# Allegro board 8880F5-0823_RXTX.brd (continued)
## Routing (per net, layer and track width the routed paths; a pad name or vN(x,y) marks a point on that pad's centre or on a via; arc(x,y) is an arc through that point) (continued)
UDBGND:
  vias: v1(117.69,130.81) v1(118.49,128.27) v1(128.57,149.86) v1(128.57,146.05) v1(128.57,138.43) v1(128.57,134.62) v1(130.51,142.24) v1(224.37,298.45) v1(225.17,295.91) v1(452.68,137.92) v1(452.68,134.11) v1(452.68,130.3) v1(454.61,145.54) v1(454.61,141.73) v1(473.29,130.81) v1(474.09,128.27) v1(484.87,130.71) v1(485.12,128.27) v1(512.11,238.76) v1(512.11,234.95) v1(512.11,231.14) v1(512.11,227.33) v1(548.37,300.89) v1(548.62,298.45) v1(557.36,300.99) v1(558.16,298.45)
UT1_UP5V:
  vias: v1(115.19,128.27) v1(115.99,130.81) v1(175.7,264.1) v1(175.7,250.38) v1(175.7,236.67) v1(175.7,222.95) v1(175.7,209.49) v1(175.7,195.52) v1(175.7,182.06) v1(175.7,168.6) v1(175.7,154.88) v1(175.7,141.67) v1(192.47,264.1) v1(192.47,250.38) v1(192.47,236.67) v1(192.47,222.95) v1(192.47,209.49) v1(192.47,195.52) v1(192.47,182.06) v1(192.47,168.6) v1(192.47,154.88) v1(208.98,264.1) v1(209.23,250.38) v1(209.23,236.67) v1(209.23,222.95) v1(209.23,209.49) v1(209.23,195.52) v1(209.49,182.06) v1(209.49,168.6) v1(209.49,155.13) v1(221.87,295.91) v1(222.67,298.45) v1(232.25,271.67) v1(244.8,288.61) v1(250.5,296.86) v1(256.73,132.14) v1(263.71,296.86) v1(269.94,135.19) v1(273.24,272.1) v1(277.17,296.86) v1(282.9,147.38) v1(290.64,296.86) v1(293.31,272.1) v1(303.84,296.86) v1(304.61,152.34) v1(304.61,139.64) v1(312.25,271.67) v1(317.05,296.86) v1(318.32,139.64) v1(330.51,296.86) v1(343.98,296.86) v1(354.27,138.37) v1(369.38,265.11) v1(369.38,249.11) v1(369.38,232.6) v1(369.63,297.12) v1(369.63,281.11) v1(375.22,188.15) v1(375.22,171.39) v1(376.23,217.11) v1(383.09,297.12) v1(383.09,281.11) v1(383.09,265.11) v1(383.09,249.11) v1(383.09,232.85) v1(383.73,202.38) v1(384.36,139.89) v1(388.43,188.15) v1(388.43,171.64) v1(388.43,154.88) v1(389.7,217.36) v1(396.55,297.12) v1(396.55,281.11) v1(396.55,265.37) v1(396.55,249.11) v1(396.55,233.11) v1(397.57,139.89) v1(400.24,202.38) v1(401.89,188.15) v1(401.89,171.64) v1(402.14,154.88) v1(403.41,217.61) v1(410.27,265.37) v1(410.52,297.12) v1(410.52,281.37) v1(410.52,249.11) v1(410.78,139.89) v1(415.1,171.64) v1(415.6,154.88) v1(423.61,188.92) v1(470.79,128.27) v1(471.59,130.81) v1(482.62,128.27) v1(483.17,130.71) v1(546.12,298.45) v1(546.67,300.89) v1(554.86,298.45) v1(555.66,300.99)
N26125600: length 3
  BOTTOM w0.119: R55.2 211.29,259.17 210.81,258.7 K25.3
N26125602: length 3
  BOTTOM w0.119: R56.1 211.29,256.03 210.81,256.5 K25.4
N26125604: length 3
  BOTTOM w0.119: K25.6 199.14,258.7 198.67,259.17 R57.2
N26125606: length 3
  BOTTOM w0.119: K25.5 199.14,256.5 198.67,256.03 R58.1
N26125622: length 3
  BOTTOM w0.119: R59.2 194.78,245.46 194.3,244.98 K26.3
N26125624: length 3
  BOTTOM w0.119: R60.1 194.78,242.31 194.3,242.78 K26.4
N26125626: length 3
  BOTTOM w0.119: R61.2 182.16,245.46 182.63,244.98 K26.6
N26125628: length 3
  BOTTOM w0.119: R62.1 182.16,242.31 182.63,242.78 K26.5
N26125644: length 3
  BOTTOM w0.119: K27.5 165.87,242.78 165.4,242.31 R66.1
N26125646: length 3
  BOTTOM w0.119: R65.2 165.4,245.46 165.87,244.98 K27.6
N26125685: length 3
  BOTTOM w0.119: K22.6 199.4,244.98 198.92,245.46 R45.2
N26125687: length 3
  BOTTOM w0.119: K22.5 199.4,242.78 198.92,242.31 R46.1
N26125689: length 3
  BOTTOM w0.119: K23.3 194.3,231.27 194.78,231.74 R47.2
N26125691: length 3
  BOTTOM w0.119: R48.1 194.78,228.6 194.3,229.07 K23.4
N26125693: length 3
  BOTTOM w0.119: R49.2 182.16,231.74 182.63,231.27 K23.6
N26125695: length 3
  BOTTOM w0.119: K23.5 182.63,229.07 182.16,228.6 R50.1
N26125711: length 3
  BOTTOM w0.119: R51.2 178.01,231.74 177.54,231.27 K24.3
N26125713: length 3
  BOTTOM w0.119: K24.4 177.54,229.07 178.01,228.6 R52.1
N26125715: length 3
  BOTTOM w0.119: K24.6 165.87,231.27 165.4,231.74 R53.2
N26125717: length 3
  BOTTOM w0.119: K24.5 165.87,229.07 165.4,228.6 R54.1
N26125746: length 3
  BOTTOM w0.119: R102.2 211.54,245.46 211.07,244.98 K22.3
N26125748: length 3
  BOTTOM w0.119: R103.1 211.54,242.31 211.07,242.78 K22.4
N26125750: length 3
  BOTTOM w0.119: R104.2 178.01,245.46 177.54,244.98 K27.3
N26125752: length 3
  BOTTOM w0.119: K27.4 177.54,242.78 178.01,242.31 R105.1
N26323523: length 3
  BOTTOM w0.119: K17.3 255.9,298.7 255.43,299.17 R71.2
N26323525: length 3
  BOTTOM w0.119: K17.4 258.1,298.7 258.58,299.17 R72.1
N26323527: length 3
  BOTTOM w0.119: R74.1 258.58,286.55 258.1,287.03 K17.5
N26323529: length 3
  BOTTOM w0.119: K17.6 255.9,287.03 255.43,286.55 R73.2
N26323531: length 3
  BOTTOM w0.119: K21.3 282.57,298.7 282.1,299.17 R75.2
N26323533: length 3
  BOTTOM w0.119: K21.4 284.77,298.7 285.25,299.17 R76.1
N26323535: length 3
  BOTTOM w0.119: K21.5 284.77,287.03 285.25,286.55 R78.1
N26323537: length 3
  BOTTOM w0.119: K21.6 282.57,287.03 282.1,286.55 R77.2
N26323539: length 3
  BOTTOM w0.119: K29.3 177.54,258.7 178.01,259.17 R79.2
N26323541: length 3
  BOTTOM w0.119: R80.1 178.01,256.03 177.54,256.5 K29.4
N26323543: length 3
  BOTTOM w0.119: K29.6 165.87,258.7 165.4,259.17 R43.2
N26323545: length 3
  BOTTOM w0.119: R44.1 165.4,256.03 165.87,256.5 K29.5
N26323547: length 3
  BOTTOM w0.119: R63.2 194.78,259.17 194.3,258.7 K30.3
N26323549: length 3
  BOTTOM w0.119: K30.4 194.3,256.5 194.78,256.03 R64.1
N26323551: length 3
  BOTTOM w0.119: R101.1 182.16,256.03 182.63,256.5 K30.5
N26323553: length 3
  BOTTOM w0.119: K30.6 182.63,258.7 182.16,259.17 R100.2
N26325241: length 3
  BOTTOM w0.119: R67.2 239.87,286.3 239.4,286.77 K16.3
N26325243: length 3
  BOTTOM w0.119: K16.4 237.2,286.77 236.72,286.3 R68.1
N26325245: length 3
  BOTTOM w0.119: K16.5 237.2,298.44 236.72,298.92 R70.1
N26325247: length 3
  BOTTOM w0.119: R69.2 239.87,298.92 239.4,298.44 K16.6
N26326910: length 3
  BOTTOM w0.119: K6.5 338.11,287.03 338.59,286.55 R30.1
N26326941: length 3
  BOTTOM w0.119: R27.2 335.44,299.17 335.91,298.7 K6.3
N26326943: length 3
  BOTTOM w0.119: K6.4 338.11,298.7 338.59,299.17 R28.1
N26326945: length 3
  BOTTOM w0.119: K6.6 335.91,287.03 335.44,286.55 R29.2
N26326947: length 3
  BOTTOM w0.119: R34.1 325.12,286.55 324.65,287.03 K7.5
N26326959: length 3
  BOTTOM w0.119: K7.3 322.45,298.7 321.98,299.17 R31.2
N26326961: length 3
  BOTTOM w0.119: R32.1 325.12,299.17 324.65,298.7 K7.4
N26326963: length 3
  BOTTOM w0.119: R33.2 321.98,286.55 322.45,287.03 K7.6
N26327095: length 3
  BOTTOM w0.119: K11.3 287.91,270.26 288.38,269.79 R39.2
N26327097: length 3
  BOTTOM w0.119: K11.4 285.71,270.26 285.24,269.79 R40.1
N26327099: length 3
  BOTTOM w0.119: K8.5 271.31,287.03 271.78,286.55 R38.1
N26327103: length 3
  BOTTOM w0.119: R37.2 268.64,286.55 269.11,287.03 K8.6
N26327105: length 3
  BOTTOM w0.119: K11.6 287.91,281.93 288.38,282.41 R41.2
N26327107: length 3
  BOTTOM w0.119: R42.1 285.24,282.41 285.71,281.93 K11.5
N26328546: length 3
  BOTTOM w0.119: K5.5 351.58,287.03 352.05,286.55 R26.1
N26328550: length 3
  BOTTOM w0.119: R23.2 348.9,299.17 349.38,298.7 K5.3
N26328552: length 3
  BOTTOM w0.119: R24.1 352.05,299.17 351.58,298.7 K5.4
N26328554: length 3
  BOTTOM w0.119: K5.6 349.38,287.03 348.9,286.55 R25.2
N26330264: length 3
  BOTTOM w0.119: K3.5 298.24,287.03 298.71,286.55 R18.1
N26330266: length 3
  BOTTOM w0.119: R17.2 295.56,286.55 296.04,287.03 K3.6
N26330268: length 3
  BOTTOM w0.119: R16.1 298.71,299.17 298.24,298.7 K3.4
N26330270: length 3
  BOTTOM w0.119: K3.3 296.04,298.7 295.56,299.17 R15.2
N26330276: length 3
  BOTTOM w0.119: K1.5 165.87,215.35 165.4,214.88 R10.1
N26330278: length 3
  BOTTOM w0.119: K1.6 165.87,217.55 165.4,218.02 R9.2
N26330280: length 3
  BOTTOM w0.119: R8.1 178.01,214.88 177.54,215.35 K1.4
N26330282: length 3
  BOTTOM w0.119: R7.2 178.01,218.02 177.54,217.55 K1.3
N26330286: length 3
  BOTTOM w0.119: K2.3 211.07,231.27 211.54,231.74 R11.2
N26330288: length 3
  BOTTOM w0.119: R12.1 211.54,228.6 211.07,229.07 K2.4
N26330290: length 3
  BOTTOM w0.119: R22.1 311.92,286.55 311.44,287.03 K4.5
N26330294: length 3
  BOTTOM w0.119: R19.2 308.77,299.17 309.24,298.7 K4.3
N26330296: length 3
  BOTTOM w0.119: K4.4 311.44,298.7 311.92,299.17 R20.1
N26330298: length 3
  BOTTOM w0.119: K4.6 309.24,287.03 308.77,286.55 R21.2
N26330300: length 3
  BOTTOM w0.119: R14.1 198.92,228.6 199.4,229.07 K2.5
N26330302: length 3
  BOTTOM w0.119: R13.2 198.92,231.74 199.4,231.27 K2.6
N26336828:
  vias: v1(222.38,273.82) v1(222.38,272.66) v1(224.65,271.67)
N26336832:
  vias: v1(222.38,275.98) v1(222.38,274.82) v1(224.65,276.97)
N26336834:
  vias: v1(221.21,276.98) v1(222.38,276.98)
N26336836:
  vias: v1(221.21,271.66) v1(222.38,271.66)
N26486525: length 3
  BOTTOM w0.119: UNK2K25.3 401.95,234.94 401.48,235.42 UNK2R55.2
N26486526: length 3
  BOTTOM w0.119: UNK2R56.1 404.63,235.42 404.15,234.94 UNK2K25.4
N26486527: length 3
  BOTTOM w0.119: UNK2R57.2 401.48,222.8 401.95,223.27 UNK2K25.6
N26486528: length 3
  BOTTOM w0.119: UNK2R58.1 404.63,222.8 404.15,223.27 UNK2K25.5
N26486530: length 3
  BOTTOM w0.119: UNK2K26.3 395.1,219.2 394.62,219.67 UNK2R59.2
N26486531: length 3
  BOTTOM w0.119: UNK2R60.1 397.77,219.67 397.3,219.2 UNK2K26.4
N26486532: length 3
  BOTTOM w0.119: UNK2R61.2 394.62,207.05 395.1,207.52 UNK2K26.6
N26486533: length 3
  BOTTOM w0.119: UNK2R62.1 397.77,207.05 397.3,207.52 UNK2K26.5
N26486535: length 3
  BOTTOM w0.119: UNK2K27.5 383.83,207.27 384.31,206.8 UNK2R66.1
N26486536: length 3
  BOTTOM w0.119: UNK2K27.6 381.63,207.27 381.16,206.8 UNK2R65.2
N26486543: length 3
  BOTTOM w0.119: UNK2R45.2 374.3,222.29 374.78,222.76 UNK2K22.6
N26486544: length 3
  BOTTOM w0.119: UNK2R46.1 377.45,222.29 376.98,222.76 UNK2K22.5
N26486545: length 3
  BOTTOM w0.119: UNK2K23.3 388.49,234.69 388.02,235.16 UNK2R47.2
N26486546: length 3
  BOTTOM w0.119: UNK2R48.1 391.16,235.16 390.69,234.69 UNK2K23.4
N26486547: length 3
  BOTTOM w0.119: UNK2R49.2 388.02,222.55 388.49,223.02 UNK2K23.6
N26486548: length 3
  BOTTOM w0.119: UNK2R50.1 391.16,222.55 390.69,223.02 UNK2K23.5
N26486550: length 3
  BOTTOM w0.119: UNK2K24.3 388.49,250.95 388.02,251.42 UNK2R51.2
N26486551: length 3
  BOTTOM w0.119: UNK2K24.4 390.69,250.95 391.16,251.42 UNK2R52.1
N26486552: length 3
  BOTTOM w0.119: UNK2R53.2 388.02,238.8 388.49,239.27 UNK2K24.6
N26486553: length 3
  BOTTOM w0.119: UNK2R54.1 391.16,238.8 390.69,239.27 UNK2K24.5
N26486568: length 3
  BOTTOM w0.119: UNK2K22.3 374.78,234.44 374.3,234.91 UNK2R102.2
N26486569: length 3
  BOTTOM w0.119: UNK2K22.4 376.98,234.44 377.45,234.91 UNK2R103.1
N26486570: length 3
  BOTTOM w0.119: UNK2R104.2 381.16,219.41 381.63,218.94 UNK2K27.3
N26486571: length 3
  BOTTOM w0.119: UNK2R105.1 384.31,219.41 383.83,218.94 UNK2K27.4
N26486686:
  vias: v1(465.57,235.71)
N26486691:
  vias: v1(468.62,235.71)
N26486726:
  vias: v1(374.56,299.91) v1(375.03,297.12)
N26486727:
  vias: v1(377.23,297.12) v1(377.7,299.91)
N26486728:
  vias: v1(377.23,289.12) v1(377.7,286.32)
N26486729:
  vias: v1(374.56,286.32) v1(375.03,289.12)
N26486730:
  vias: v1(401.48,299.91) v1(401.95,297.12)
N26486731:
  vias: v1(404.15,297.12) v1(404.63,299.91)
N26486732:
  vias: v1(404.15,289.12) v1(404.63,286.32)
N26486733:
  vias: v1(401.48,286.32) v1(401.95,289.12)
N26486734: length 3
  BOTTOM w0.119: UNK2R79.2 374.3,251.42 374.78,250.95 UNK2K29.3
N26486735: length 3
  BOTTOM w0.119: UNK2K29.4 376.98,250.95 377.45,251.42 UNK2R80.1
N26486736: length 3
  BOTTOM w0.119: UNK2K29.6 374.78,239.27 374.3,238.8 UNK2R43.2
N26486737: length 3
  BOTTOM w0.119: UNK2K29.5 376.98,239.27 377.45,238.8 UNK2R44.1
N26486738: length 3
  BOTTOM w0.119: UNK2R63.2 415.45,251.42 415.92,250.95 UNK2K30.3
N26486739: length 3
  BOTTOM w0.119: UNK2K30.4 418.12,250.95 418.6,251.42 UNK2R64.1
N26486740: length 3
  BOTTOM w0.119: UNK2K30.5 418.12,239.27 418.6,238.8 UNK2R101.1
N26486741: length 3
  BOTTOM w0.119: UNK2R100.2 415.45,238.8 415.92,239.27 UNK2K30.6
N26486822:
  vias: v1(374.3,267.91) v1(374.78,265.11)
N26486823:
  vias: v1(376.98,265.11) v1(377.45,267.91)
N26486824:
  vias: v1(376.98,257.11) v1(377.45,254.32)
N26486825:
  vias: v1(374.3,254.32) v1(374.78,257.11)
N26486847:
  vias: v1(404.15,273.11) v1(404.63,270.32)
N26486849:
  vias: v1(401.48,283.91) v1(401.95,281.11)
N26486850:
  vias: v1(404.15,281.11) v1(404.63,283.91)
N26486851:
  vias: v1(401.48,270.32) v1(401.95,273.11)
N26486852:
  vias: v1(390.69,273.11) v1(391.16,270.32)
N26486854:
  vias: v1(388.02,283.91) v1(388.49,281.11)
N26486855:
  vias: v1(390.69,281.11) v1(391.16,283.91)
N26486856:
  vias: v1(388.02,270.32) v1(388.49,273.11)
N26486898:
  vias: v1(415.2,268.16)
N26486899:
  vias: v1(418.34,268.16)
N26486900:
  vias: v1(390.69,289.12) v1(391.16,286.32)
N26486902:
  vias: v1(388.02,286.32) v1(388.49,289.12)
N26486903:
  vias: v1(415.2,254.57) v1(415.67,257.37)
N26486904:
  vias: v1(417.87,257.37) v1(418.34,254.57)
N26486946:
  vias: v1(404.15,257.37) v1(404.63,254.57)
N26486948:
  vias: v1(401.48,268.16) v1(401.95,265.37)
N26486949:
  vias: v1(404.15,265.37) v1(404.63,268.16)
N26486950:
  vias: v1(401.48,254.57) v1(401.95,257.37)
N26486971: length 3
  BOTTOM w0.119: UNK2R18.1 404.63,238.8 404.15,239.27 UNK2K3.5
N26486972: length 3
  BOTTOM w0.119: UNK2R17.2 401.48,238.8 401.95,239.27 UNK2K3.6
N26486973: length 3
  BOTTOM w0.119: UNK2K3.4 404.15,250.95 404.63,251.42 UNK2R16.1
N26486974: length 3
  BOTTOM w0.119: UNK2K3.3 401.95,250.95 401.48,251.42 UNK2R15.2
N26486977: length 3
  BOTTOM w0.119: UNK2K1.5 418.12,287.28 418.6,286.81 UNK2R10.1
N26486978: length 3
  BOTTOM w0.119: UNK2R9.2 415.45,286.81 415.92,287.28 UNK2K1.6
N26486979: length 3
  BOTTOM w0.119: UNK2R8.1 418.6,299.42 418.12,298.95 UNK2K1.4
N26486980: length 3
  BOTTOM w0.119: UNK2R7.2 415.45,299.42 415.92,298.95 UNK2K1.3
N26486982:
  vias: v1(415.45,284.16)
N26486983:
  vias: v1(418.6,284.16)
N26486984:
  vias: v1(377.23,273.11) v1(377.7,270.32)
N26486986:
  vias: v1(374.56,283.91) v1(375.03,281.11)
N26486987:
  vias: v1(377.23,281.11) v1(377.7,283.91)
N26486988:
  vias: v1(374.56,270.32) v1(375.03,273.11)
N26486989: length 3
  BOTTOM w0.119: UNK2R14.1 418.6,271.01 418.12,271.48 UNK2K2.5
N26486990: length 3
  BOTTOM w0.119: UNK2R13.2 415.45,270.98 415.92,271.45 UNK2K2.6
N26487182:
  vias: v1(456.25,233.88)
N26487183:
  vias: v1(451.68,233.88)
N26487190:
  vias: v1(302.38,273.82) v1(302.38,272.66) v1(304.65,271.67)
N26487192:
  vias: v1(302.38,275.98) v1(302.38,274.82) v1(304.65,276.97)
N26487193:
  vias: v1(301.21,276.98) v1(302.38,276.98)
N26487194:
  vias: v1(301.21,271.66) v1(302.38,271.66)
N26487223:
  vias: v1(451.62,232.41)
N26487224:
  vias: v1(451.62,224.79)
N26487285:
  vias: v1(483.1,233.68)
N26487289:
  vias: v1(483.1,241.3)
N26491412:
  vias: v1(491.1,226.67)
N26491416:
  vias: v1(490.86,212.91)
N26491418:
  vias: v1(485.8,212.91)
N26491425:
  vias: v1(477.53,218.59)
N26491459:
  vias: v1(477.43,204.98)
N26491497:
  vias: v1(485.8,226.62)
N26495382: length 3
  BOTTOM w0.119: UNK3R55.2 211.79,163.67 211.32,163.2 UNK3K25.3
N26495383: length 3
  BOTTOM w0.119: UNK3R56.1 211.79,160.52 211.32,161 UNK3K25.4
N26495384: length 3
  BOTTOM w0.119: UNK3K25.6 199.65,163.2 199.18,163.67 UNK3R57.2
N26495385: length 3
  BOTTOM w0.119: UNK3K25.5 199.65,161 199.18,160.52 UNK3R58.1
N26495387: length 3
  BOTTOM w0.119: UNK3R59.2 194.78,163.67 194.3,163.2 UNK3K26.3
N26495388: length 3
  BOTTOM w0.119: UNK3R60.1 194.78,160.52 194.3,161 UNK3K26.4
N26495389: length 3
  BOTTOM w0.119: UNK3K26.6 182.63,163.2 182.16,163.67 UNK3R61.2
N26495390: length 3
  BOTTOM w0.119: UNK3K26.5 182.63,161 182.16,160.52 UNK3R62.1
N26495392: length 3
  BOTTOM w0.119: UNK3R66.1 199.18,173.99 199.65,174.46 UNK3K27.5
N26495393: length 3
  BOTTOM w0.119: UNK3K27.6 199.65,176.66 199.18,177.13 UNK3R65.2
N26495400: length 3
  BOTTOM w0.119: UNK3R45.2 199.18,150.21 199.65,149.73 UNK3K22.6
N26495401: length 3
  BOTTOM w0.119: UNK3R46.1 199.18,147.06 199.65,147.53 UNK3K22.5
N26495402: length 3
  BOTTOM w0.119: UNK3K23.3 177.54,136.27 178.01,136.74 UNK3R47.2
N26495403: length 3
  BOTTOM w0.119: UNK3K23.4 177.54,134.07 178.01,133.6 UNK3R48.1
N26495404: length 3
  BOTTOM w0.119: UNK3K23.6 165.87,136.27 165.4,136.74 UNK3R49.2
N26495405: length 3
  BOTTOM w0.119: UNK3R50.1 165.4,133.6 165.87,134.07 UNK3K23.5
N26495407: length 3
  BOTTOM w0.119: UNK3K24.3 194.3,149.48 194.78,149.95 UNK3R51.2
N26495408: length 3
  BOTTOM w0.119: UNK3R52.1 194.78,146.81 194.3,147.28 UNK3K24.4
N26495409: length 3
  BOTTOM w0.119: UNK3K24.6 182.63,149.48 182.16,149.95 UNK3R53.2
N26495410: length 3
  BOTTOM w0.119: UNK3K24.5 182.63,147.28 182.16,146.81 UNK3R54.1
N26495425: length 3
  BOTTOM w0.119: UNK3K22.3 211.32,149.73 211.79,150.21 UNK3R102.2
N26495426: length 3
  BOTTOM w0.119: UNK3K22.4 211.32,147.53 211.79,147.06 UNK3R103.1
N26495427: length 3
  BOTTOM w0.119: UNK3R104.2 211.79,177.13 211.32,176.66 UNK3K27.3
N26495428: length 3
  BOTTOM w0.119: UNK3R105.1 211.79,173.99 211.32,174.46 UNK3K27.4
N26495583: length 3
  BOTTOM w0.119: UNK3K17.3 177.54,190.12 178.01,190.59 UNK3R71.2
N26495584: length 3
  BOTTOM w0.119: UNK3R72.1 178.01,187.45 177.54,187.92 UNK3K17.4
N26495585: length 3
  BOTTOM w0.119: UNK3K17.5 165.87,187.92 165.4,187.45 UNK3R74.1
N26495586: length 3
  BOTTOM w0.119: UNK3R73.2 165.4,190.59 165.87,190.12 UNK3K17.6
N26495587: length 3
  BOTTOM w0.119: UNK3R75.2 211.54,190.59 211.07,190.12 UNK3K21.3
N26495588: length 3
  BOTTOM w0.119: UNK3R76.1 211.54,187.45 211.07,187.92 UNK3K21.4
N26495589: length 3
  BOTTOM w0.119: UNK3K21.5 199.4,187.92 198.92,187.45 UNK3R78.1
N26495590: length 3
  BOTTOM w0.119: UNK3K21.6 199.4,190.12 198.92,190.59 UNK3R77.2
N26495591: length 3
  BOTTOM w0.119: UNK3R79.2 178.01,163.67 177.54,163.2 UNK3K29.3
N26495592: length 3
  BOTTOM w0.119: UNK3K29.4 177.54,161 178.01,160.52 UNK3R80.1
N26495593: length 3
  BOTTOM w0.119: UNK3R43.2 165.4,163.67 165.87,163.2 UNK3K29.6
N26495594: length 3
  BOTTOM w0.119: UNK3R44.1 165.4,160.52 165.87,161 UNK3K29.5
N26495595: length 3
  BOTTOM w0.119: UNK3K30.3 177.54,149.48 178.01,149.95 UNK3R63.2
N26495596: length 3
  BOTTOM w0.119: UNK3R64.1 178.01,146.81 177.54,147.28 UNK3K30.4
N26495597: length 3
  BOTTOM w0.119: UNK3K30.5 165.87,147.28 165.4,146.81 UNK3R101.1
N26495598: length 3
  BOTTOM w0.119: UNK3R100.2 165.4,149.95 165.87,149.48 UNK3K30.6
N26495679: length 3
  BOTTOM w0.119: UNK3R67.2 211.54,204.56 211.07,204.09 UNK3K16.3
N26495680: length 3
  BOTTOM w0.119: UNK3R68.1 211.54,201.42 211.07,201.89 UNK3K16.4
N26495681: length 3
  BOTTOM w0.119: UNK3K16.5 199.4,201.89 198.92,201.42 UNK3R70.1
N26495682: length 3
  BOTTOM w0.119: UNK3K16.6 199.4,204.09 198.92,204.56 UNK3R69.2
N26495704: length 3
  BOTTOM w0.119: UNK3K6.5 199.4,215.35 198.92,214.88 UNK3R30.1
N26495706: length 3
  BOTTOM w0.119: UNK3R27.2 211.54,218.02 211.07,217.55 UNK3K6.3
N26495707: length 3
  BOTTOM w0.119: UNK3K6.4 211.07,215.35 211.54,214.88 UNK3R28.1
N26495708: length 3
  BOTTOM w0.119: UNK3K6.6 199.4,217.55 198.92,218.02 UNK3R29.2
N26495709: length 3
  BOTTOM w0.119: UNK3R34.1 182.16,201.42 182.63,201.89 UNK3K7.5
N26495711: length 3
  BOTTOM w0.119: UNK3K7.3 194.3,204.09 194.78,204.56 UNK3R31.2
N26495712: length 3
  BOTTOM w0.119: UNK3R32.1 194.78,201.42 194.3,201.89 UNK3K7.4
N26495713: length 3
  BOTTOM w0.119: UNK3R33.2 182.16,204.56 182.63,204.09 UNK3K7.6
N26495755: length 3
  BOTTOM w0.119: UNK3R39.2 178.01,204.56 177.54,204.09 UNK3K11.3
N26495756: length 3
  BOTTOM w0.119: UNK3K11.4 177.54,201.89 178.01,201.42 UNK3R40.1
N26495757: length 3
  BOTTOM w0.119: UNK3R38.1 182.16,187.45 182.63,187.92 UNK3K8.5
N26495759: length 3
  BOTTOM w0.119: UNK3K8.6 182.63,190.12 182.16,190.59 UNK3R37.2
N26495760: length 3
  BOTTOM w0.119: UNK3R41.2 165.4,204.56 165.87,204.09 UNK3K11.6
N26495761: length 3
  BOTTOM w0.119: UNK3R42.1 165.4,201.42 165.87,201.89 UNK3K11.5
N26495803: length 3
  BOTTOM w0.119: UNK3K5.5 182.63,215.35 182.16,214.88 UNK3R26.1
N26495805: length 3
  BOTTOM w0.119: UNK3R23.2 194.78,218.02 194.3,217.55 UNK3K5.3
N26495806: length 3
  BOTTOM w0.119: UNK3R24.1 194.78,214.88 194.3,215.35 UNK3K5.4
N26495807: length 3
  BOTTOM w0.119: UNK3R25.2 182.16,218.02 182.63,217.55 UNK3K5.6
N26495828: length 3
  BOTTOM w0.119: UNK3K3.5 262.34,145.03 261.87,145.5 UNK3R18.1
N26495829: length 3
  BOTTOM w0.119: UNK3R17.2 265.01,145.5 264.54,145.03 UNK3K3.6
N26495830: length 3
  BOTTOM w0.119: UNK3R16.1 261.87,132.88 262.34,133.36 UNK3K3.4
N26495831: length 3
  BOTTOM w0.119: UNK3K3.3 264.54,133.36 265.01,132.88 UNK3R15.2
N26495834: length 3
  BOTTOM w0.119: UNK3K1.5 275.3,157.22 274.82,157.69 UNK3R10.1
N26495835: length 3
  BOTTOM w0.119: UNK3K1.6 277.5,157.22 277.97,157.69 UNK3R9.2
N26495836: length 3
  BOTTOM w0.119: UNK3K1.4 275.3,145.55 274.82,145.08 UNK3R8.1
N26495837: length 3
  BOTTOM w0.119: UNK3K1.3 277.5,145.55 277.97,145.08 UNK3R7.2
N26495839: length 3
  BOTTOM w0.119: UNK3K2.3 251.33,130.31 251.81,129.84 UNK3R11.2
N26495840: length 3
  BOTTOM w0.119: UNK3R12.1 248.66,129.84 249.13,130.31 UNK3K2.4
N26495841: length 3
  BOTTOM w0.119: UNK3K4.5 165.93,174.46 165.46,173.99 UNK3R22.1
N26495843: length 3
  BOTTOM w0.119: UNK3K4.3 177.54,176.66 178.01,177.13 UNK3R19.2
N26495844:
  vias: v1(175.7,174.46) v1(178.5,173.99)
N26495845: length 3
  BOTTOM w0.119: UNK3R21.2 165.4,177.13 165.87,176.66 UNK3K4.6
N26495846: length 3
  BOTTOM w0.119: UNK3K2.5 249.13,141.98 248.66,142.45 UNK3R14.1
N26495847: length 3
  BOTTOM w0.119: UNK3R13.2 251.81,142.45 251.33,141.98 UNK3K2.6
N26504239: length 3
  BOTTOM w0.119: UNK4R55.2 393.35,190.46 393.83,189.99 UNK4K25.3
N26504240: length 3
  BOTTOM w0.119: UNK4K25.4 396.03,189.99 396.5,190.46 UNK4R56.1
N26504241: length 3
  BOTTOM w0.119: UNK4R57.2 393.35,177.84 393.83,178.31 UNK4K25.6
N26504242: length 3
  BOTTOM w0.119: UNK4R58.1 396.5,177.84 396.03,178.31 UNK4K25.5
N26504244: length 3
  BOTTOM w0.119: UNK4K26.3 407.29,189.99 406.82,190.46 UNK4R59.2
N26504245: length 3
  BOTTOM w0.119: UNK4K26.4 409.49,189.99 409.96,190.46 UNK4R60.1
N26504246: length 3
  BOTTOM w0.119: UNK4K26.6 407.29,178.31 406.82,177.84 UNK4R61.2
N26504247: length 3
  BOTTOM w0.119: UNK4R62.1 409.96,177.84 409.49,178.31 UNK4K26.5
N26504249: length 3
  BOTTOM w0.119: UNK4R66.1 383.29,161.08 382.82,161.55 UNK4K27.5
N26504250: length 3
  BOTTOM w0.119: UNK4R65.2 380.15,161.08 380.62,161.55 UNK4K27.6
N26504257: length 3
  BOTTOM w0.119: UNK4K22.6 373.89,196.98 373.42,197.45 UNK4R45.2
N26504258: length 3
  BOTTOM w0.119: UNK4K22.5 373.89,194.78 373.42,194.31 UNK4R46.1
N26504259: length 3
  BOTTOM w0.119: UNK4R47.2 402.55,197.45 402.08,196.98 UNK4K23.3
N26504260: length 3
  BOTTOM w0.119: UNK4R48.1 402.55,194.31 402.08,194.78 UNK4K23.4
N26504261: length 3
  BOTTOM w0.119: UNK4K23.6 390.4,196.98 389.93,197.45 UNK4R49.2
N26504262: length 3
  BOTTOM w0.119: UNK4K23.5 390.4,194.78 389.93,194.31 UNK4R50.1
N26504264: length 3
  BOTTOM w0.119: UNK4K24.3 356.1,132.97 356.57,133.44 UNK4R51.2
N26504265: length 3
  BOTTOM w0.119: UNK4K24.4 356.1,130.77 356.57,130.3 UNK4R52.1
N26504266: length 3
  BOTTOM w0.119: UNK4K24.6 344.43,132.97 343.96,133.44 UNK4R53.2
N26504267: length 3
  BOTTOM w0.119: UNK4R54.1 343.96,130.3 344.43,130.77 UNK4K24.5
N26504282: length 3
  BOTTOM w0.119: UNK4K22.3 385.57,196.98 386.04,197.45 UNK4R102.2
N26504283: length 3
  BOTTOM w0.119: UNK4K22.4 385.57,194.78 386.04,194.31 UNK4R103.1
N26504284: length 3
  BOTTOM w0.119: UNK4K27.3 380.62,173.22 380.15,173.69 UNK4R104.2
N26504285: length 3
  BOTTOM w0.119: UNK4R105.1 383.29,173.69 382.82,173.22 UNK4K27.4
N26504400:
  vias: v1(465.57,192.28)
N26504405:
  vias: v1(468.62,192.28)
N26504440: length 3
  BOTTOM w0.119: UNK4K17.3 416.18,141.73 415.71,142.2 UNK4R71.2
N26504441: length 3
  BOTTOM w0.119: UNK4R72.1 418.85,142.2 418.38,141.73 UNK4K17.4
N26504442: length 3
  BOTTOM w0.119: UNK4K17.5 418.38,130.05 418.85,129.58 UNK4R74.1
N26504443: length 3
  BOTTOM w0.119: UNK4R73.2 415.71,129.58 416.18,130.05 UNK4K17.6
N26504444: length 3
  BOTTOM w0.119: UNK4R75.2 389.29,142.2 389.76,141.73 UNK4K21.3
N26504445: length 3
  BOTTOM w0.119: UNK4R76.1 392.43,142.2 391.96,141.73 UNK4K21.4
N26504446: length 3
  BOTTOM w0.119: UNK4K21.5 391.96,130.05 392.43,129.58 UNK4R78.1
N26504447: length 3
  BOTTOM w0.119: UNK4R77.2 389.29,129.58 389.76,130.05 UNK4K21.6
N26504448: length 3
  BOTTOM w0.119: UNK4R79.2 406.82,173.95 407.29,173.48 UNK4K29.3
N26504449: length 3
  BOTTOM w0.119: UNK4K29.4 409.49,173.48 409.96,173.95 UNK4R80.1
N26504450: length 3
  BOTTOM w0.119: UNK4R43.2 406.82,161.33 407.29,161.8 UNK4K29.6
N26504451: length 3
  BOTTOM w0.119: UNK4K29.5 409.49,161.8 409.96,161.33 UNK4R44.1
N26504452: length 3
  BOTTOM w0.119: UNK4K30.3 310.01,154.17 309.53,154.64 UNK4R63.2
N26504453: length 3
  BOTTOM w0.119: UNK4R64.1 312.68,154.64 312.21,154.17 UNK4K30.4
N26504454: length 3
  BOTTOM w0.119: UNK4K30.5 312.21,142.5 312.68,142.03 UNK4R101.1
N26504455: length 3
  BOTTOM w0.119: UNK4K30.6 310.01,142.5 309.53,142.03 UNK4R100.2
N26504536: length 3
  BOTTOM w0.119: UNK4R67.2 393.35,173.95 393.83,173.48 UNK4K16.3
N26504537: length 3
  BOTTOM w0.119: UNK4K16.4 396.03,173.48 396.5,173.95 UNK4R68.1
N26504538: length 3
  BOTTOM w0.119: UNK4K16.5 396.03,161.8 396.5,161.33 UNK4R70.1
N26504539: length 3
  BOTTOM w0.119: UNK4R69.2 393.35,161.33 393.83,161.8 UNK4K16.6
N26504561: length 3
  BOTTOM w0.119: UNK4R30.1 396.5,144.57 396.03,145.04 UNK4K6.5
N26504563: length 3
  BOTTOM w0.119: UNK4R27.2 393.35,157.18 393.83,156.71 UNK4K6.3
N26504564: length 3
  BOTTOM w0.119: UNK4K6.4 396.03,156.71 396.5,157.18 UNK4R28.1
N26504565: length 3
  BOTTOM w0.119: UNK4R29.2 393.35,144.57 393.83,145.04 UNK4K6.6
N26504566: length 3
  BOTTOM w0.119: UNK4K7.5 413.77,181.32 413.3,180.84 UNK4R34.1
N26504568: length 3
  BOTTOM w0.119: UNK4R31.2 425.92,183.99 425.44,183.52 UNK4K7.3
N26504569: length 3
  BOTTOM w0.119: UNK4K7.4 425.44,181.32 425.92,180.84 UNK4R32.1
N26504570: length 3
  BOTTOM w0.119: UNK4K7.6 413.77,183.52 413.3,183.99 UNK4R33.2
N26504612: length 3
  BOTTOM w0.119: UNK4K11.3 380.62,189.99 380.15,190.46 UNK4R39.2
N26504613: length 3
  BOTTOM w0.119: UNK4R40.1 383.29,190.46 382.82,189.99 UNK4K11.4
N26504614: length 3
  BOTTOM w0.119: UNK4K8.5 405.17,130.05 405.64,129.58 UNK4R38.1
N26504616: length 3
  BOTTOM w0.119: UNK4K8.6 402.97,130.05 402.5,129.58 UNK4R37.2
N26504617: length 3
  BOTTOM w0.119: UNK4K11.6 380.62,178.31 380.15,177.84 UNK4R41.2
N26504618: length 3
  BOTTOM w0.119: UNK4K11.5 382.82,178.31 383.29,177.84 UNK4R42.1
N26504660: length 3
  BOTTOM w0.119: UNK4R26.1 423.68,144.57 423.2,145.04 UNK4K5.5
N26504662: length 3
  BOTTOM w0.119: UNK4R23.2 420.53,157.18 421,156.71 UNK4K5.3
N26504663: length 3
  BOTTOM w0.119: UNK4R24.1 423.68,157.18 423.2,156.71 UNK4K5.4
N26504664: length 3
  BOTTOM w0.119: UNK4R25.2 420.53,144.57 421,145.04 UNK4K5.6
N26504685: length 3
  BOTTOM w0.119: UNK4K3.5 325.92,129.8 326.39,129.33 UNK4R18.1
N26504686: length 3
  BOTTOM w0.119: UNK4K3.6 323.72,129.8 323.25,129.33 UNK4R17.2
N26504687: length 3
  BOTTOM w0.119: UNK4K3.4 325.92,141.47 326.39,141.94 UNK4R16.1
N26504688: length 3
  BOTTOM w0.119: UNK4R15.2 323.25,141.94 323.72,141.47 UNK4K3.3
N26504691: length 3
  BOTTOM w0.119: UNK4R10.1 423.17,161.33 422.7,161.8 UNK4K1.5
N26504692: length 3
  BOTTOM w0.119: UNK4R9.2 420.02,161.33 420.5,161.8 UNK4K1.6
N26504693: length 3
  BOTTOM w0.119: UNK4K1.4 422.7,173.48 423.17,173.95 UNK4R8.1
N26504694: length 3
  BOTTOM w0.119: UNK4R7.2 420.02,173.95 420.5,173.48 UNK4K1.3
N26504696: length 3
  BOTTOM w0.119: UNK4K2.3 407.54,156.71 407.07,157.18 UNK4R11.2
N26504697: length 3
  BOTTOM w0.119: UNK4R12.1 410.21,157.18 409.74,156.71 UNK4K2.4
N26504698: length 3
  BOTTOM w0.119: UNK4K4.5 411.01,207.78 411.48,207.31 UNK4R22.1
N26504700: length 3
  BOTTOM w0.119: UNK4R19.2 408.34,219.92 408.81,219.45 UNK4K4.3
N26504701: length 3
  BOTTOM w0.119: UNK4R20.1 411.48,219.92 411.01,219.45 UNK4K4.4
N26504702: length 3
  BOTTOM w0.119: UNK4R21.2 408.34,207.31 408.81,207.78 UNK4K4.6
N26504703: length 3
  BOTTOM w0.119: UNK4R14.1 410.21,144.57 409.74,145.04 UNK4K2.5
N26504704: length 3
  BOTTOM w0.119: UNK4R13.2 407.07,144.57 407.54,145.04 UNK4K2.6
N26504896:
  vias: v1(456.25,190.45)
N26504897:
  vias: v1(451.68,190.45)
N26504937:
  vias: v1(451.62,188.98)
N26504938:
  vias: v1(451.62,181.36)
N26504999:
  vias: v1(483.1,190.25)
N26505003:
  vias: v1(483.1,197.87)
N26509126:
  vias: v1(491.1,183.24)
N26509130:
  vias: v1(490.86,169.47)
N26509132:
  vias: v1(485.8,169.47)
N26509139:
  vias: v1(477.53,175.15)
N26509173:
  vias: v1(477.43,161.55)
N26509211:
  vias: v1(485.8,183.19)

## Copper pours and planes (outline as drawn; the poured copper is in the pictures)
GND on L03_SIGNAL, L05_SIGNAL, L07_SIGNAL, L28_SIGNAL, L30_SIGNAL: 1.27,1.27 1.27,427.99 205.8,427.99 217.17,422.33 228.54,427.99 353.12,427.99 364.49,422.33 375.86,427.99 580.39,427.99 580.39,1.27 302.2,1.27 290.83,6.93 279.46,1.27
(no net) on L32_SIGNAL: 1.27,1.27 1.27,427.99 205.8,427.99 217.17,422.33 228.54,427.99 353.12,427.99 364.49,422.33 375.86,427.99 580.39,427.99 580.39,1.27 302.2,1.27 290.83,6.93 279.46,1.27
Net_7 on L02_DGND: 8.32,299.68 8.32,129.45 568.71,129.45 568.71,299.68
Net_8 on L02_DGND: 230.83,264.63 230.83,224.63 270.83,224.63 270.83,264.63
Net_8 on L02_DGND: 230.83,204.63 230.83,164.63 270.83,164.63 270.83,204.63
Net_8 on L02_DGND: 310.83,204.63 310.83,164.63 350.83,164.63 350.83,204.63
Net_8 on L02_DGND: 310.83,264.63 310.83,224.63 350.83,224.63 350.83,264.63

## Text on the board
User.Comments: CR_SS_6 | CR_2_2 | CR_RELAY_19 | CR_4_2 | CR_3_1 | CR_2_3 | CR_UNNAMED_2 | CR_UNNAMED_3 | CR_QQ_28 | CR_A_23 | CR_5_1 | CR_5_2 | CR_QQ_12 | CR_QQ_11 | CR_A_28 | CR_A_21 | CR_A_25 | CR_A_26 | CR_A_30 | CR_A_32 | CR_A_22 | CR_A_24 | CR_A_27 | CR_A_29 | CR_A_31 | CR_A_20
